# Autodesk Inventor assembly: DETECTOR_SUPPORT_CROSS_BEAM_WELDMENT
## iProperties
Shininess: 64.0
Length Units: 11272
Angle Units: 11279
Time Units: 11290
Mass Units: 11286
Length Display Precision: 3
Angle Display Precision: 2
Compacted: True
Part Number: DETECTOR_SUPPORT_CROSS_BEAM_WELDMENT
Document SubType Name: Assembly
Created: 2004-08
Designer: John Blackburn
Manufacturer: Standard
Standards Organization: Custom
Density: 0.0
Volumn: 0.0
Area: 0.0
PropertySet Name: Model Information
Control State: 0
Master: False
Checked Out: False
Author: John Blackburn
